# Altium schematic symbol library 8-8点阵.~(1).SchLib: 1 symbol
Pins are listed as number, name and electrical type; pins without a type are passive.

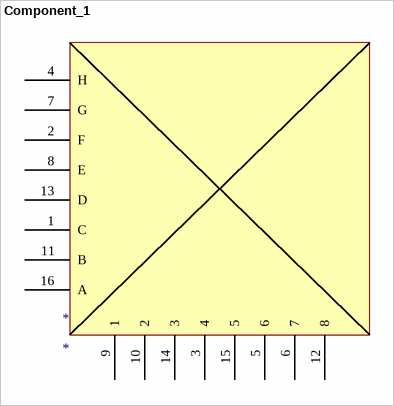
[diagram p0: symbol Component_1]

## Component_1
designator *
pins: 1 C, 2 F, 3 4, 4 H, 5 6, 6 7, 7 G, 8 E, 9 1, 10 2, 11 B, 12 8, 13 D, 14 3, 15 5, 16 A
